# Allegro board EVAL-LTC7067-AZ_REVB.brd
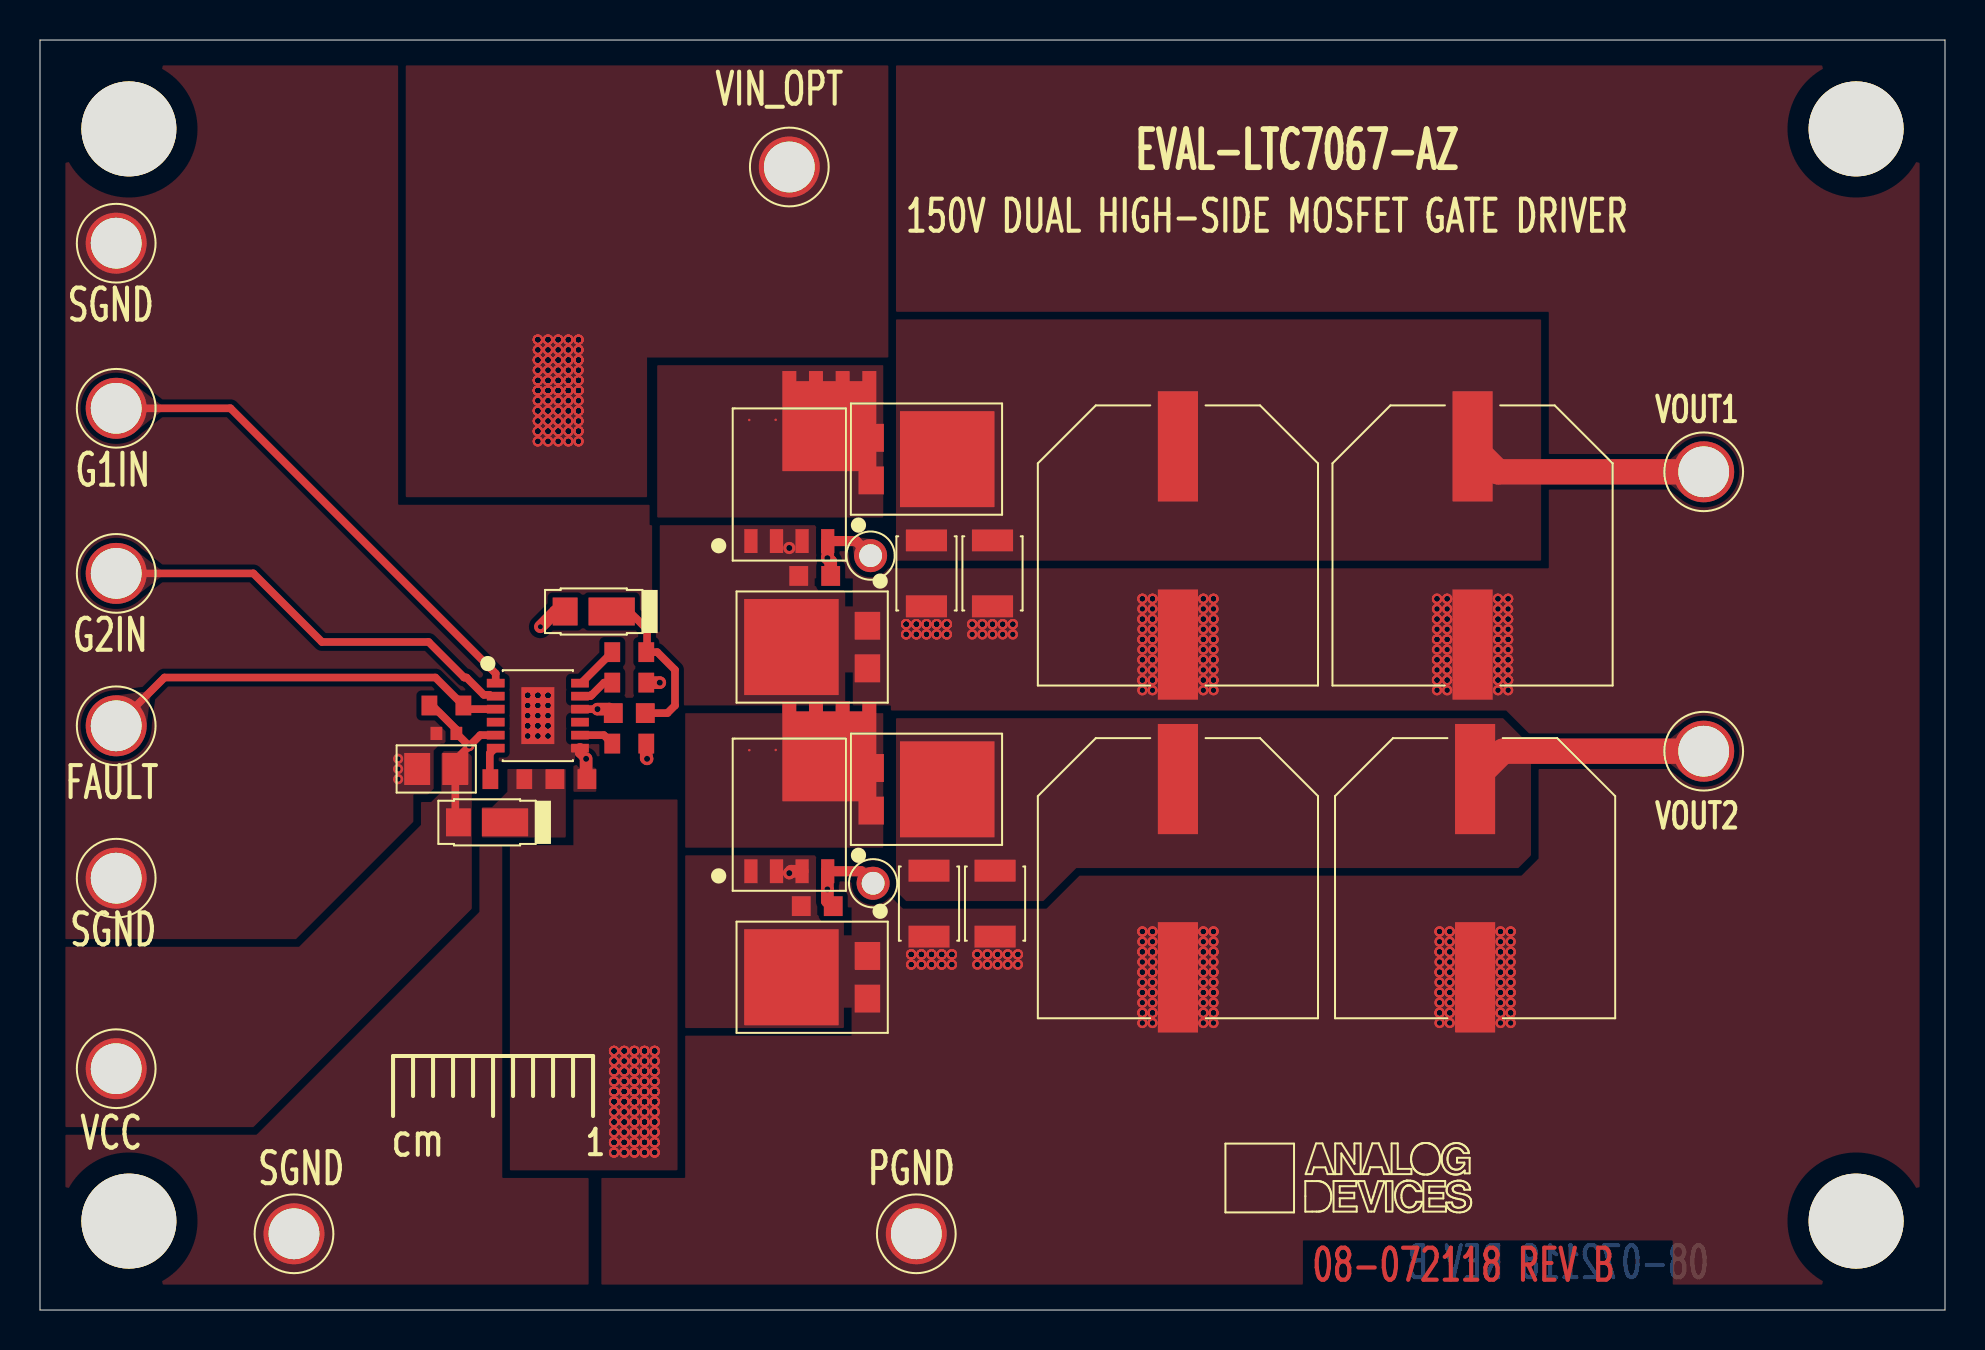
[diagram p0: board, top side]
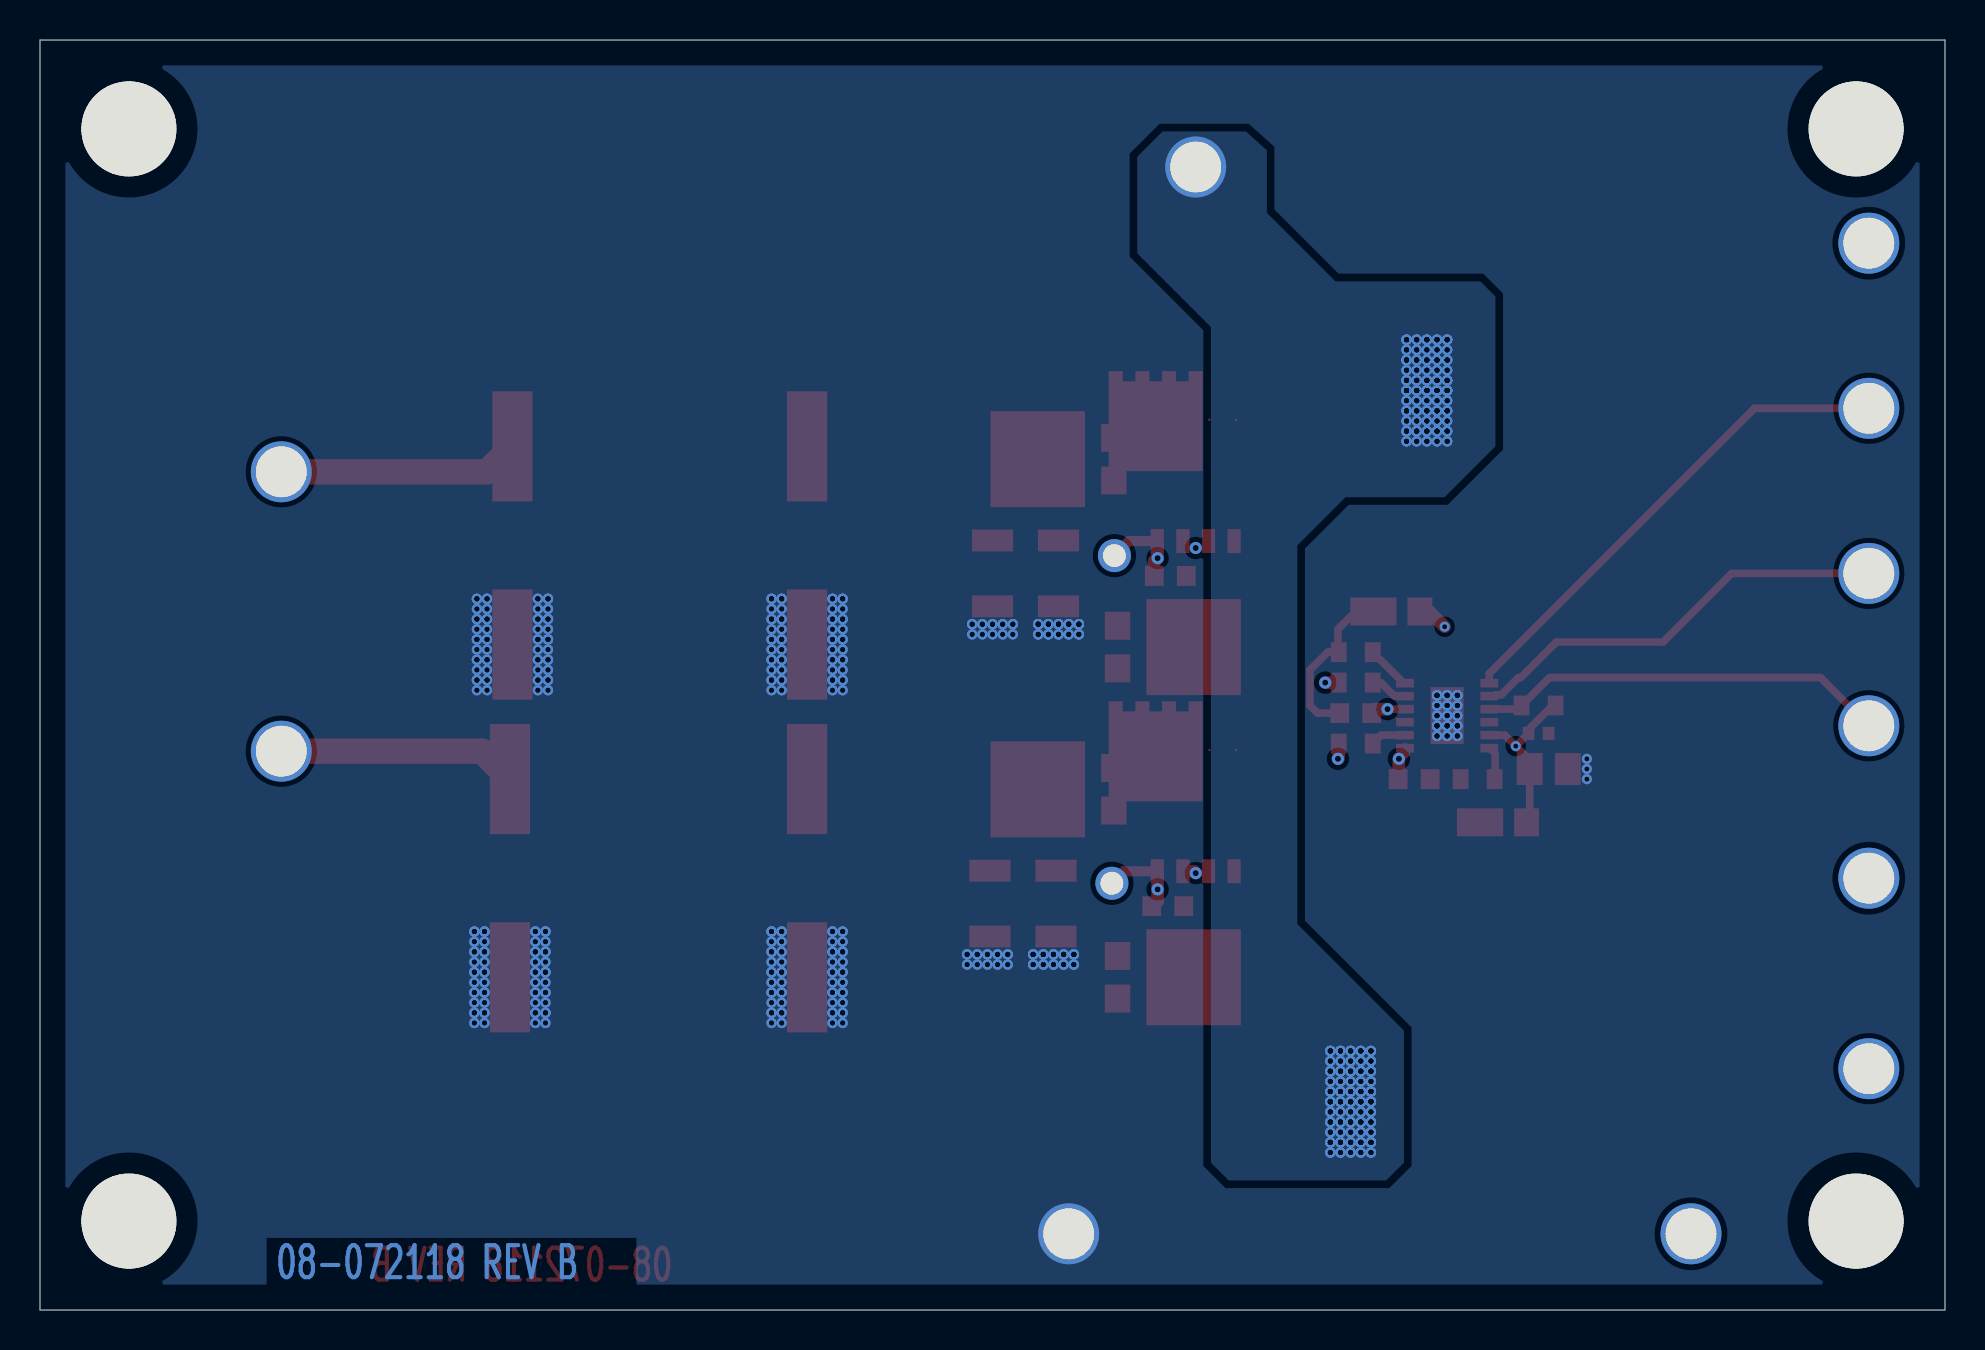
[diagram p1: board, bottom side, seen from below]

Outline 95.25 x 63.5 mm; copper layers: TOP, LAYER_2, LAYER_3, BOTTOM. Coordinates in mm from the lower left corner of the outline.
Outline path: 0,63.5 0,0 95.25,0 95.25,63.5 0,63.5

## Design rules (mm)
constraint set DEFAULT: min track width 0.203

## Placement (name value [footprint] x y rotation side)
C1  1uF  [C0402]  20.32 28.83 180 top
C2  10uF  [C0805H53]  19.81 27.05 180 top
C3  1uF  [C0603]  26.54 26.54 0 top
C4  1uF  [C0603]  29.46 29.84 180 top
C5  3300PF  [C0603]  38.73 36.7 180 top
C6  3300PF  [C0603]  38.86 20.19 180 top
C7  10UF  [C1210H106]  44.32 36.83 270 top
C8  10UF  [C1210H106]  47.75 20.32 270 top
C9  10UF  [C1210H106]  47.62 36.83 270 top
C10  10UF  [C1210H106]  44.45 20.32 270 top
C11  47UF  [CPLSMSQ531H551]  56.9 38.23 270 top
C12  47UF  [CPLSMSQ531H551]  56.9 21.59 270 top
C13  47UF  [CPLSMSQ531H551]  71.63 38.23 270 top
C14  47UF  [CPLSMSQ531H551]  71.75 21.59 270 top
D1  V10PM15-M3/H  [TO-277A]  44.32 42.55 0 top
D2  V10PM15-M3/H  [TO-277A]  44.32 26.04 0 top
D3  V10PM15-M3/H  [TO-277A]  38.61 33.15 180 top
D4  V10PM15-M3/H  [TO-277A]  38.61 16.64 180 top
D5  S115FP  [SOD123HE]  22.35 24.38 180 top
D6  S115FP  [SOD123HE]  27.69 34.92 180 top
G1  TESTPAD  [TPC65D45]  41.53 37.72 0 top
G2  TESTPAD  [TPC65D45]  41.66 21.34 0 top
NOREF  -  []  -219.18 315.6 0 top
NOREF#2  -  []  0 0 90 top
NOREF#3  -  []  -240.03 120.65 0 top
NOREF#4  -  []  51.44 332.11 0 top
NOREF#5  -  []  20.95 5.71 0 top
NOREF#6  -  [unnamed#2]  4.45 4.45 0 top
NOREF#7  -  []  25.53 -11.3 0 top
NOREF#8  -  []  -90.81 -85.09 0 top
NOREF#9  -  []  -247.01 -158.75 0 top
NOREF#10  -  []  -0.13 0.13 0 top
NOREF#11  -  []  -247.01 -158.75 0 top
NOREF#12  -  []  -220 266.04 0 top
NOREF#13  -  []  -217.17 341 0 top
NOREF#14  -  [unnamed#2]  90.81 59.05 0 top
NOREF#15  -  [unnamed#2]  4.45 59.05 0 top
NOREF#16  -  []  323.85 306.07 0 top
NOREF#17  -  []  -247.01 -158.75 0 top
NOREF#18  -  [unnamed#2]  90.81 4.45 0 top
Q1  BSC160N15NS5ATMA1  [SON8]  37.47 41.27 0 top
Q2  BSC160N15NS5ATMA1  [SON8]  37.47 24.77 0 top
R2  100K  [R0603]  20.32 30.23 0 top
R5  0  [R0603]  23.37 26.54 0 top
R6  0  [R0603]  29.46 31.37 180 top
R7  0  [R0603]  29.46 32.89 180 top
R8  0  [R0603]  29.46 28.32 180 top
TP1  2501-2-00-80-00-00-07-0  [CNMILLMAX2501]  3.81 45.09 0 top
TP2  2501-2-00-80-00-00-07-0  [CNMILLMAX2501]  3.81 36.83 0 top
TP3  2501-2-00-80-00-00-07-0  [CNMILLMAX2501]  3.81 12.06 0 top
TP4  2501-2-00-80-00-00-07-0  [CNMILLMAX2501]  37.47 57.15 0 top
TP5  2501-2-00-80-00-00-07-0  [CNMILLMAX2501]  43.81 3.81 0 top
TP6  2501-2-00-80-00-00-07-0  [CNMILLMAX2501]  3.81 21.59 0 top
TP7  2501-2-00-80-00-00-07-0  [CNMILLMAX2501]  83.19 41.91 0 top
TP8  2501-2-00-80-00-00-07-0  [CNMILLMAX2501]  83.19 27.94 0 top
TP9  2501-2-00-80-00-00-07-0  [CNMILLMAX2501]  3.81 53.34 0 top
TP10  2501-2-00-80-00-00-07-0  [CNMILLMAX2501]  12.7 3.81 0 top
TP11  2501-2-00-80-00-00-07-0  [CNMILLMAX2501]  3.81 29.21 0 top
U1  LTC7067RMSE#WPBF  [MSOP12_PAD2_845X1_651_05-08-1666]  24.89 29.72 270 top

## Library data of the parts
C1 = CAP: User Part Number: UPN; Tolerance: 20; alternate symbols: (C0402L); part number: CAP_SM-1UF,16V,20,E020695,C0402; tolerance: 20
C2 = CAP: Tolerance: 10; User Part Number: UPN; alternate symbols: (); part number: CAP_SM-10UF,16V,10,E006166,C0805H53; tolerance: 10
C3 C4 = CAP: User Part Number: UPN; Tolerance: 10; alternate symbols: (C0603L); part number: CAP_SM-1UF,16V,10,E020111,C0603; tolerance: 10
C5 C6 = CAP: User Part Number: UPN; Tolerance: 10; alternate symbols: (C0603L); part number: CAP_SM-3300PF,25V,10,E058968,C0603; tolerance: 10
C7-C10 = CAP: Tolerance: 10; User Part Number: UPN; alternate symbols: (C1210L); part number: CAP_SM-10UF,100V,10,E044329,C1210H106; tolerance: 10
C11-C14 = CAPP: Tolerance: 20; User Part Number: UPN; alternate symbols: (); part number: CAPP_SM-47UF,100V,20,E049289,CPLSMSQ531H551; tolerance: 20
D1-D4 = DIOSCHOTTKY_3P: User Part Number: UPN; Tolerance: N/A; alternate symbols: (); part number: DIOSCHOTTKY_3P_SM-V10PM15-M3/H,150V,N/A,E057965,TO-277A; tolerance: N/A
D5 D6 = DIOSCHOTTKY: User Part Number: UPN; Tolerance: N/A; alternate symbols: (); part number: DIOSCHOTTKY_SM-S115FP,150V,N/A,E046225,SOD123HE; tolerance: N/A
G1 G2 = NCTESTPAD: Tolerance: N/A; User Part Number: UPN; alternate symbols: (); part number: NCTESTPAD_TH-TESTPAD,E013404,TPC65D45; tolerance: N/A
Q1 Q2 = TRANNMOSFET_8P_V2: Tolerance: N/A; User Part Number: UPN; alternate symbols: (); part number: TRANNMOSFET_8P_V2_SM-BSC160N15NS5ATMA1,E051660,SON8; tolerance: N/A
R2 = RES: User Part Number: UPN; Tolerance: 1; alternate symbols: (R0603L); part number: RES_SM-100K,E010279,1/10W,1,R0603; tolerance: 1
R5-R8 = RES: User Part Number: UPN; Tolerance: N/A; alternate symbols: (R0603L); part number: RES_SM-0,E005803,N/A,N/A,R0603; tolerance: N/A
TP1-TP11 = CNTP1P: User Part Number: UPN; Tolerance: N/A; alternate symbols: (); part number: CNTP1P_TH-2501-2-00-80-00-00-07-0,E031108,CNMILLMAX2501; tolerance: N/A
U1 = ADLTC7067: Tolerance: N/A; User Part Number: UPN; alternate symbols: (); part number: ADLTC7067_SM-LTC7067RMSE#WPBF,E057879,MSOP12_PAD2_845X1_651_05-08-1666; tolerance: N/A

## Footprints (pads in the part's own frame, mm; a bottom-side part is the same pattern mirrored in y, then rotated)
C0402
  rect 0.584x0.66 smd: 1(-0.5,0) 2(0.5,0)
C0603
  rect 0.94x0.991 smd: 1(-0.8,0) 2(0.8,0)
C0805H53
  rect 1.295x1.6 smd: 1(-0.953,0) 2(0.953,0)
C1210H106
  rect 1.092x2.057 smd: 1(-1.646,0) 2(1.646,0)
CNMILLMAX2501
  round 3.048 hole 2.54: 1(0,0)
CPLSMSQ531H551
  rect 5.512x2.007 smd: N(4.956,0) P(-4.956,0)
MSOP12_PAD2_845X1_651_05-08-1666
  rect 0.432x0.889 smd: 1(-1.625,-2.107) 2(-0.975,-2.107) 3(-0.325,-2.107) 4(0.325,-2.107) 5(0.975,-2.107) 6(1.625,-2.107) 7(1.625,2.107) 8(0.975,2.107) 9(0.325,2.107) 10(-0.325,2.107) 11(-0.975,2.107) 12(-1.625,2.107)
  rect 2.845x1.651 smd: 13(0,0)
R0603
  rect 0.787x0.991 smd: 1(-0.85,0) 2(0.85,0)
SOD123HE
  rect 1.245x1.397 smd: A(1.431,0)
  rect 2.311x1.397 smd: C(-0.897,0)
SON8
  rect 0.66x1.194 smd: 1(-1.92,-2.828) 2(-0.64,-2.828) 3(0.64,-2.828) 4(1.92,-2.828)
  custom 1.175x1.175 smd: 5(2,3.171)
  round 0.127 smd: 6(0.678,3.211) 7(-0.68,3.236) 8(-2.002,3.223)
TO-277A
  rect 1.27x1.397 smd: 1(-2.765,-1.065) 2(-2.765,1.065)
  rect 4.724x4.801 smd: 3(1.038,0)
TPC65D45
  round 1.651 hole 1.143: 1(0,0)
unnamed#2
  round 4.75 hole 4.75 unplated: (0,0)

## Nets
GND_SIGNAL: C1.2(N2) C2.2(N2) C3.2(N2) C4.2(N2) C5.2(N2) C6.2(N2) C7.2(N2) C8.2(N2) C9.2(N2) C10.2(N2) C11.N(N2) C12.N(N2) C13.N(N2) C14.N(N2) D3.1 D3.2 D3.3(C) D4.1 D4.2 D4.3(C) Q1.1 Q1.2 Q1.3(S3) Q2.1 Q2.2 Q2.3(S3) TP5.1(N1) TP6.1(N1) TP9.1(N1) TP10.1(N1) U1.7 U1.10 U1.13
VCC: C1.1 C2.1 D5.A(P) D6.A(P) R2.1 TP3.1(N1) U1.5(VCC)
VIN_OPT: TP4.1(N1)
G1: C5.1 G1.1(N1) Q1.4 R6.1
G2: C6.1 G2.1(N1) Q2.4 R8.1
Q1_D: D1.1 D1.2 Q1.5 Q1.6 Q1.7 Q1.8
Q2_D: D2.1 D2.2 Q2.5 Q2.6 Q2.7 Q2.8
UNNAMED_2_ADLTC7067_I79_FLTN: R2.2(N2) TP11.1(N1) U1.3
UNNAMED_2_ADLTC7067_I79_G1: R6.2(N2) U1.11
UNNAMED_2_ADLTC7067_I79_G1IN: TP1.1(N1) U1.1
UNNAMED_2_ADLTC7067_I79_G1VCC: R7.2(N2) U1.12
UNNAMED_2_ADLTC7067_I79_G2: R8.2(N2) U1.8
UNNAMED_2_ADLTC7067_I79_G2IN: TP2.1(N1) U1.2
UNNAMED_2_ADLTC7067_I79_G2VCC: R5.1 U1.6
UNNAMED_2_CAP_I57_N1: C7.1 C9.1 C11.P C13.P D1.3(C) TP7.1(N1)
UNNAMED_2_CAP_I59_N1: C8.1 C10.1 C12.P C14.P D2.3(C) TP8.1(N1)
UNNAMED_2_DIOSCHOTTKY_I13_N: C3.1 D5.C R5.2(N2)
UNNAMED_2_DIOSCHOTTKY_I25_N: C4.1 D6.C R7.1

Pads without a net: U1 4 9

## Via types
v1: diameter 0.61, hole 0.305, TOP to BOTTOM, 8 vias
v2: diameter 0.508, hole 0.254, TOP to BOTTOM, 1469 vias

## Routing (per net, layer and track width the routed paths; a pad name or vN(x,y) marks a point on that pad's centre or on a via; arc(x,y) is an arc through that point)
GND_SIGNAL: length 33.7
  TOP w0.381: U1.10 v1(27.88,30.04)
  TOP w0.508: v1(27.3,27.56) 27,27.87 U1.7
  TOP w0.635: Q2.3 37.56,21.94 v1(37.47,21.84) ; v1(27.3,27.56) 27.3,26.58 C3.2 ; C4.2 28.47,30.04 v1(27.88,30.04)
  LAYER_3 w0.635: v1(37.47,38.1) 37.47,36.32 33.4,32.26 30.09,32.26 v1(27.88,30.04) ; v1(27.3,27.56) 29.08,27.56 29.92,28.4 30.7,28.4 31.24,27.86 31.24,23.75 33.15,21.84 v1(37.47,21.84)
  vias: v2(17.91,27.56) v2(17.91,27.05) v2(17.91,26.54) v2(24.38,30.73) v2(24.38,30.73) v2(24.38,30.73) v2(24.38,30.73) v2(24.38,30.73) v2(24.38,30.73) v2(24.38,30.73) v2(24.38,30.73) v2(24.38,30.23) v2(24.38,30.23) v2(24.38,30.23) v2(24.38,30.23) v2(24.38,29.72) v2(24.38,29.72) v2(24.38,29.72) v2(24.38,29.72) v2(24.38,29.21) v2(24.38,29.21) v2(24.38,29.21) v2(24.38,29.21) v2(24.38,29.21) v2(24.38,29.21) v2(24.38,29.21) v2(24.38,29.21) v2(24.38,28.7) v2(24.38,28.7) v2(24.38,28.7) v2(24.38,28.7) v2(24.89,30.73) v2(24.89,30.73) v2(24.89,30.73) v2(24.89,30.73) v2(24.89,30.73) v2(24.89,30.73) v2(24.89,30.73) v2(24.89,30.73) v2(24.89,30.23) v2(24.89,30.23) v2(24.89,30.23) v2(24.89,30.23) v2(24.89,29.72) v2(24.89,29.72) v2(24.89,29.72) v2(24.89,29.72) v2(24.89,29.21) v2(24.89,29.21) v2(24.89,29.21) v2(24.89,29.21) v2(24.89,29.21) v2(24.89,29.21) v2(24.89,29.21) v2(24.89,29.21) v2(24.89,28.7) v2(24.89,28.7) v2(24.89,28.7) v2(24.89,28.7) v2(25.4,30.73) v2(25.4,30.73) v2(25.4,30.73) v2(25.4,30.73) v2(25.4,30.73) v2(25.4,30.73) v2(25.4,30.73) v2(25.4,30.73) v2(25.4,30.23) v2(25.4,30.23) v2(25.4,30.23) v2(25.4,30.23) v2(25.4,29.72) v2(25.4,29.72) v2(25.4,29.72) v2(25.4,29.72) v2(25.4,29.21) v2(25.4,29.21) v2(25.4,29.21) v2(25.4,29.21) v2(25.4,29.21) v2(25.4,29.21) v2(25.4,29.21) v2(25.4,29.21) v2(25.4,28.7) v2(25.4,28.7) v2(25.4,28.7) v2(25.4,28.7) v2(43.31,34.29) v2(43.31,34.29) v2(43.31,34.29) v2(43.31,34.29) v2(43.31,34.29) v2(43.31,34.29) v2(43.31,34.29) v2(43.31,34.29) v2(43.31,33.78) v2(43.31,33.78) v2(43.31,33.78) v2(43.31,33.78) v2(43.56,17.78) v2(43.56,17.78) v2(43.56,17.78) v2(43.56,17.78) v2(43.56,17.78) v2(43.56,17.78) v2(43.56,17.78) v2(43.56,17.78) v2(43.56,17.27) v2(43.56,17.27) v2(43.56,17.27) v2(43.56,17.27) v2(43.81,34.29) v2(43.81,34.29) v2(43.81,34.29) v2(43.81,34.29) v2(43.81,34.29) v2(43.81,34.29) v2(43.81,34.29) v2(43.81,34.29) v2(43.81,33.78) v2(43.81,33.78) v2(43.81,33.78) v2(43.81,33.78) v2(44.07,17.78) v2(44.07,17.78) v2(44.07,17.78) v2(44.07,17.78) v2(44.07,17.78) v2(44.07,17.78) v2(44.07,17.78) v2(44.07,17.78) v2(44.07,17.27) v2(44.07,17.27) v2(44.07,17.27) v2(44.07,17.27) v2(44.32,34.29) v2(44.32,34.29) v2(44.32,34.29) v2(44.32,34.29) v2(44.32,34.29) v2(44.32,34.29) v2(44.32,34.29) v2(44.32,34.29) v2(44.32,33.78) v2(44.32,33.78) v2(44.32,33.78) v2(44.32,33.78) v2(44.58,17.78) v2(44.58,17.78) v2(44.58,17.78) v2(44.58,17.78) v2(44.58,17.78) v2(44.58,17.78) v2(44.58,17.78) v2(44.58,17.78) v2(44.58,17.27) v2(44.58,17.27) v2(44.58,17.27) v2(44.58,17.27) v2(44.83,34.29) v2(44.83,34.29) v2(44.83,34.29) v2(44.83,34.29) v2(44.83,34.29) v2(44.83,34.29) v2(44.83,34.29) v2(44.83,34.29) v2(44.83,33.78) v2(44.83,33.78) v2(44.83,33.78) v2(44.83,33.78) v2(45.09,17.78) v2(45.09,17.78) v2(45.09,17.78) v2(45.09,17.78) v2(45.09,17.78) v2(45.09,17.78) v2(45.09,17.78) v2(45.09,17.78) v2(45.09,17.27) v2(45.09,17.27) v2(45.09,17.27) v2(45.09,17.27) v2(45.34,34.29) v2(45.34,34.29) v2(45.34,34.29) v2(45.34,34.29) v2(45.34,34.29) v2(45.34,34.29) v2(45.34,34.29) v2(45.34,34.29) v2(45.34,33.78) v2(45.34,33.78) v2(45.34,33.78) v2(45.34,33.78) v2(45.59,17.78) v2(45.59,17.78) v2(45.59,17.78) v2(45.59,17.78) v2(45.59,17.78) v2(45.59,17.78) v2(45.59,17.78) v2(45.59,17.78) v2(45.59,17.27) v2(45.59,17.27) v2(45.59,17.27) v2(45.59,17.27) v2(46.61,34.29) v2(46.61,34.29) v2(46.61,34.29) v2(46.61,34.29) v2(46.61,33.78) v2(46.61,33.78) v2(46.86,17.78) v2(46.86,17.78) v2(46.86,17.78) v2(46.86,17.78) v2(46.86,17.27) v2(46.86,17.27) v2(47.12,34.29) v2(47.12,34.29) v2(47.12,34.29) v2(47.12,34.29) v2(47.12,33.78) v2(47.12,33.78) v2(47.37,17.78) v2(47.37,17.78) v2(47.37,17.78) v2(47.37,17.78) v2(47.37,17.27) v2(47.37,17.27) v2(47.62,34.29) v2(47.62,34.29) v2(47.62,34.29) v2(47.62,34.29) v2(47.62,33.78) v2(47.62,33.78) v2(47.88,17.78) v2(47.88,17.78) v2(47.88,17.78) v2(47.88,17.78) v2(47.88,17.27) v2(47.88,17.27) v2(48.13,34.29) v2(48.13,34.29) v2(48.13,34.29) v2(48.13,34.29) v2(48.13,33.78) v2(48.13,33.78) v2(48.39,17.78) v2(48.39,17.78) v2(48.39,17.78) v2(48.39,17.78) v2(48.39,17.27) v2(48.39,17.27) v2(48.64,34.29) v2(48.64,34.29) v2(48.64,34.29) v2(48.64,34.29) v2(48.64,33.78) v2(48.64,33.78) v2(48.9,17.78) v2(48.9,17.78) v2(48.9,17.78) v2(48.9,17.78) v2(48.9,17.27) v2(48.9,17.27) v2(55.12,35.56) v2(55.12,35.56) v2(55.12,35.56) v2(55.12,35.56) v2(55.12,35.05) v2(55.12,35.05) v2(55.12,34.54) v2(55.12,34.54) v2(55.12,34.54) v2(55.12,34.54) v2(55.12,34.04) v2(55.12,34.04) v2(55.12,33.53) v2(55.12,33.53) v2(55.12,33.53) v2(55.12,33.53) v2(55.12,33.02) v2(55.12,33.02) v2(55.12,32.51) v2(55.12,32.51) v2(55.12,32.51) v2(55.12,32.51) v2(55.12,32) v2(55.12,32) v2(55.12,31.5) v2(55.12,31.5) v2(55.12,31.5) v2(55.12,31.5) v2(55.12,30.99) v2(55.12,30.99) v2(55.12,18.92) v2(55.12,18.92) v2(55.12,18.92) v2(55.12,18.92) v2(55.12,18.41) v2(55.12,18.41) v2(55.12,17.91) v2(55.12,17.91) v2(55.12,17.91) v2(55.12,17.91) v2(55.12,17.4) v2(55.12,17.4) v2(55.12,16.89) v2(55.12,16.89) v2(55.12,16.89) v2(55.12,16.89) v2(55.12,16.38) v2(55.12,16.38) v2(55.12,15.88) v2(55.12,15.88) v2(55.12,15.88) v2(55.12,15.88) v2(55.12,15.37) v2(55.12,15.37) v2(55.12,14.86) v2(55.12,14.86) v2(55.12,14.86) v2(55.12,14.86) v2(55.12,14.35) v2(55.12,14.35) v2(55.63,35.56) v2(55.63,35.56) v2(55.63,35.56) v2(55.63,35.56) v2(55.63,35.05) v2(55.63,35.05) v2(55.63,34.54) v2(55.63,34.54) v2(55.63,34.54) v2(55.63,34.54) v2(55.63,34.04) v2(55.63,34.04) v2(55.63,33.53) v2(55.63,33.53) v2(55.63,33.53) v2(55.63,33.53) v2(55.63,33.02) v2(55.63,33.02) v2(55.63,32.51) v2(55.63,32.51) v2(55.63,32.51) v2(55.63,32.51) v2(55.63,32) v2(55.63,32) v2(55.63,31.5) v2(55.63,31.5) v2(55.63,31.5) v2(55.63,31.5) v2(55.63,30.99) v2(55.63,30.99) v2(55.63,18.92) v2(55.63,18.92) v2(55.63,18.92) v2(55.63,18.92) v2(55.63,18.41) v2(55.63,18.41) v2(55.63,17.91) v2(55.63,17.91) v2(55.63,17.91) v2(55.63,17.91) v2(55.63,17.4) v2(55.63,17.4) v2(55.63,16.89) v2(55.63,16.89) v2(55.63,16.89) v2(55.63,16.89) v2(55.63,16.38) v2(55.63,16.38) v2(55.63,15.88) v2(55.63,15.88) v2(55.63,15.88) v2(55.63,15.88) v2(55.63,15.37) v2(55.63,15.37) v2(55.63,14.86) v2(55.63,14.86) v2(55.63,14.86) v2(55.63,14.86) v2(55.63,14.35) v2(55.63,14.35) v2(58.17,35.56) v2(58.17,35.56) v2(58.17,35.56) v2(58.17,35.56) v2(58.17,35.05) v2(58.17,35.05) v2(58.17,34.54) v2(58.17,34.54) v2(58.17,34.54) v2(58.17,34.54) v2(58.17,34.04) v2(58.17,34.04) v2(58.17,33.53) v2(58.17,33.53) v2(58.17,33.53) v2(58.17,33.53) v2(58.17,33.02) v2(58.17,33.02) v2(58.17,32.51) v2(58.17,32.51) v2(58.17,32.51) v2(58.17,32.51) v2(58.17,32) v2(58.17,32) v2(58.17,31.5) v2(58.17,31.5) v2(58.17,31.5) v2(58.17,31.5) v2(58.17,30.99) v2(58.17,30.99) v2(58.17,18.92) v2(58.17,18.92) v2(58.17,18.92) v2(58.17,18.92) v2(58.17,18.41) v2(58.17,18.41) v2(58.17,17.91) v2(58.17,17.91) v2(58.17,17.91) v2(58.17,17.91) v2(58.17,17.4) v2(58.17,17.4) v2(58.17,16.89) v2(58.17,16.89) v2(58.17,16.89) v2(58.17,16.89) v2(58.17,16.38) v2(58.17,16.38) v2(58.17,15.88) v2(58.17,15.88) v2(58.17,15.88) v2(58.17,15.88) v2(58.17,15.37) v2(58.17,15.37) v2(58.17,14.86) v2(58.17,14.86) v2(58.17,14.86) v2(58.17,14.86) v2(58.17,14.35) v2(58.17,14.35) v2(58.67,35.56) v2(58.67,35.56) v2(58.67,35.56) v2(58.67,35.56) v2(58.67,35.05) v2(58.67,35.05) v2(58.67,34.54) v2(58.67,34.54) v2(58.67,34.54) v2(58.67,34.54) v2(58.67,34.04) v2(58.67,34.04) v2(58.67,33.53) v2(58.67,33.53) v2(58.67,33.53) v2(58.67,33.53) v2(58.67,33.02) v2(58.67,33.02) v2(58.67,32.51) v2(58.67,32.51) v2(58.67,32.51) v2(58.67,32.51) v2(58.67,32) v2(58.67,32) v2(58.67,31.5) v2(58.67,31.5) v2(58.67,31.5) v2(58.67,31.5) v2(58.67,30.99) v2(58.67,30.99) v2(58.67,18.92) v2(58.67,18.92) v2(58.67,18.92) v2(58.67,18.92) v2(58.67,18.41) v2(58.67,18.41) v2(58.67,17.91) v2(58.67,17.91) v2(58.67,17.91) v2(58.67,17.91) v2(58.67,17.4) v2(58.67,17.4) v2(58.67,16.89) v2(58.67,16.89) v2(58.67,16.89) v2(58.67,16.89) v2(58.67,16.38) v2(58.67,16.38) v2(58.67,15.88) v2(58.67,15.88) v2(58.67,15.88) v2(58.67,15.88) v2(58.67,15.37) v2(58.67,15.37) v2(58.67,14.86) v2(58.67,14.86) v2(58.67,14.86) v2(58.67,14.86) v2(58.67,14.35) v2(58.67,14.35) v2(69.85,35.56) v2(69.85,35.56) v2(69.85,35.56) v2(69.85,35.56) v2(69.85,35.05) v2(69.85,35.05) v2(69.85,34.54) v2(69.85,34.54) v2(69.85,34.54) v2(69.85,34.54) v2(69.85,34.04) v2(69.85,34.04) v2(69.85,33.53) v2(69.85,33.53) v2(69.85,33.53) v2(69.85,33.53) v2(69.85,33.02) v2(69.85,33.02) v2(69.85,32.51) v2(69.85,32.51) v2(69.85,32.51) v2(69.85,32.51) v2(69.85,32) v2(69.85,32) v2(69.85,31.5) v2(69.85,31.5) v2(69.85,31.5) v2(69.85,31.5) v2(69.85,30.99) v2(69.85,30.99) v2(69.98,18.92) v2(69.98,18.92) v2(69.98,18.92) v2(69.98,18.92) v2(69.98,18.41) v2(69.98,18.41) v2(69.98,17.91) v2(69.98,17.91) v2(69.98,17.91) v2(69.98,17.91) v2(69.98,17.4) v2(69.98,17.4) v2(69.98,16.89) v2(69.98,16.89) v2(69.98,16.89) v2(69.98,16.89) v2(69.98,16.38) v2(69.98,16.38) v2(69.98,15.88) v2(69.98,15.88) v2(69.98,15.88) v2(69.98,15.88) v2(69.98,15.37) v2(69.98,15.37) v2(69.98,14.86) v2(69.98,14.86) v2(69.98,14.86) v2(69.98,14.86) v2(69.98,14.35) v2(69.98,14.35) v2(70.36,35.56) v2(70.36,35.56) v2(70.36,35.56) v2(70.36,35.56) v2(70.36,35.05) v2(70.36,35.05) v2(70.36,34.54) v2(70.36,34.54) v2(70.36,34.54) v2(70.36,34.54) v2(70.36,34.04) v2(70.36,34.04) v2(70.36,33.53) v2(70.36,33.53) v2(70.36,33.53) v2(70.36,33.53) v2(70.36,33.02) v2(70.36,33.02) v2(70.36,32.51) v2(70.36,32.51) v2(70.36,32.51) v2(70.36,32.51) v2(70.36,32) v2(70.36,32) v2(70.36,31.5) v2(70.36,31.5) v2(70.36,31.5) v2(70.36,31.5) v2(70.36,30.99) v2(70.36,30.99) v2(70.48,18.92) v2(70.48,18.92) v2(70.48,18.92) v2(70.48,18.92) v2(70.48,18.41) v2(70.48,18.41) v2(70.48,17.91) v2(70.48,17.91) v2(70.48,17.91) v2(70.48,17.91) v2(70.48,17.4) v2(70.48,17.4) v2(70.48,16.89) v2(70.48,16.89) v2(70.48,16.89) v2(70.48,16.89) v2(70.48,16.38) v2(70.48,16.38) v2(70.48,15.88) v2(70.48,15.88) v2(70.48,15.88) v2(70.48,15.88) v2(70.48,15.37) v2(70.48,15.37) v2(70.48,14.86) v2(70.48,14.86) v2(70.48,14.86) v2(70.48,14.86) v2(70.48,14.35) v2(70.48,14.35) v2(72.9,35.56) v2(72.9,35.56) v2(72.9,35.56) v2(72.9,35.56) v2(72.9,35.05) v2(72.9,35.05) v2(72.9,34.54) v2(72.9,34.54) v2(72.9,34.54) v2(72.9,34.54) v2(72.9,34.04) v2(72.9,34.04) v2(72.9,33.53) v2(72.9,33.53) v2(72.9,33.53) v2(72.9,33.53) v2(72.9,33.02) v2(72.9,33.02) v2(72.9,32.51) v2(72.9,32.51) v2(72.9,32.51) v2(72.9,32.51) v2(72.9,32) v2(72.9,32) v2(72.9,31.5) v2(72.9,31.5) v2(72.9,31.5) v2(72.9,31.5) v2(72.9,30.99) v2(72.9,30.99) v2(73.03,18.92) v2(73.03,18.92) v2(73.03,18.92) v2(73.03,18.92) v2(73.03,18.41) v2(73.03,18.41) v2(73.03,17.91) v2(73.03,17.91) v2(73.03,17.91) v2(73.03,17.91) v2(73.03,17.4) v2(73.03,17.4) v2(73.03,16.89) v2(73.03,16.89) v2(73.03,16.89) v2(73.03,16.89) v2(73.03,16.38) v2(73.03,16.38) v2(73.03,15.88) v2(73.03,15.88) v2(73.03,15.88) v2(73.03,15.88) v2(73.03,15.37) v2(73.03,15.37) v2(73.03,14.86) v2(73.03,14.86) v2(73.03,14.86) v2(73.03,14.86) v2(73.03,14.35) v2(73.03,14.35) v2(73.41,35.56) v2(73.41,35.56) v2(73.41,35.56) v2(73.41,35.56) v2(73.41,35.05) v2(73.41,35.05) v2(73.41,34.54) v2(73.41,34.54) v2(73.41,34.54) v2(73.41,34.54) v2(73.41,34.04) v2(73.41,34.04) v2(73.41,33.53) v2(73.41,33.53) v2(73.41,33.53) v2(73.41,33.53) v2(73.41,33.02) v2(73.41,33.02) v2(73.41,32.51) v2(73.41,32.51) v2(73.41,32.51) v2(73.41,32.51) v2(73.41,32) v2(73.41,32) v2(73.41,31.5) v2(73.41,31.5) v2(73.41,31.5) v2(73.41,31.5) v2(73.41,30.99) v2(73.41,30.99) v2(73.53,18.92) v2(73.53,18.92) v2(73.53,18.92) v2(73.53,18.92) v2(73.53,18.41) v2(73.53,18.41) v2(73.53,17.91) v2(73.53,17.91) v2(73.53,17.91) v2(73.53,17.91) v2(73.53,17.4) v2(73.53,17.4) v2(73.53,16.89) v2(73.53,16.89) v2(73.53,16.89) v2(73.53,16.89) v2(73.53,16.38) v2(73.53,16.38) v2(73.53,15.88) v2(73.53,15.88) v2(73.53,15.88) v2(73.53,15.88) v2(73.53,15.37) v2(73.53,15.37) v2(73.53,14.86) v2(73.53,14.86) v2(73.53,14.86) v2(73.53,14.86) v2(73.53,14.35) v2(73.53,14.35)
VCC: length 18.8
  TOP w0.381: v2(21.46,28.19) 22.01,28.74 U1.5 ; v2(21.46,28.19) 20.76,27.5 C2.1 20.76,24.54 D5.A 20.92,24.42 ; v2(21.46,28.19) 20.83,28.83 C1.1 20.82,29.02 19.61,30.23 R2.1
  TOP w0.635: v2(25.02,34.16) 25.78,34.92 D6.A
  LAYER_3 w0.508: v2(21.46,28.19) 21.59,28.32 21.59,32.64 23.11,34.16 v2(25.02,34.16)
VIN_OPT:
  vias: v2(24.89,48.51) v2(24.89,48.51) v2(24.89,48.51) v2(24.89,48.51) v2(24.89,48.51) v2(24.89,48.51) v2(24.89,48.51) v2(24.89,48.51) v2(24.89,48.01) v2(24.89,48.01) v2(24.89,48.01) v2(24.89,48.01) v2(24.89,47.5) v2(24.89,47.5) v2(24.89,47.5) v2(24.89,47.5) v2(24.89,47.5) v2(24.89,47.5) v2(24.89,47.5) v2(24.89,47.5) v2(24.89,46.99) v2(24.89,46.99) v2(24.89,46.99) v2(24.89,46.99) v2(24.89,46.48) v2(24.89,46.48) v2(24.89,46.48) v2(24.89,46.48) v2(24.89,46.48) v2(24.89,46.48) v2(24.89,46.48) v2(24.89,46.48) v2(24.89,45.97) v2(24.89,45.97) v2(24.89,45.97) v2(24.89,45.97) v2(24.89,45.97) v2(24.89,45.97) v2(24.89,45.97) v2(24.89,45.97) v2(24.89,45.97) v2(24.89,45.97) v2(24.89,45.97) v2(24.89,45.97) v2(24.89,45.47) v2(24.89,45.47) v2(24.89,45.47) v2(24.89,45.47) v2(24.89,44.96) v2(24.89,44.96) v2(24.89,44.96) v2(24.89,44.96) v2(24.89,44.96) v2(24.89,44.96) v2(24.89,44.96) v2(24.89,44.96) v2(24.89,44.45) v2(24.89,44.45) v2(24.89,44.45) v2(24.89,44.45) v2(24.89,43.94) v2(24.89,43.94) v2(24.89,43.94) v2(24.89,43.94) v2(24.89,43.94) v2(24.89,43.94) v2(24.89,43.94) v2(24.89,43.94) v2(24.89,43.43) v2(24.89,43.43) v2(24.89,43.43) v2(24.89,43.43) v2(25.4,48.51) v2(25.4,48.51) v2(25.4,48.51) v2(25.4,48.51) v2(25.4,48.51) v2(25.4,48.51) v2(25.4,48.51) v2(25.4,48.51) v2(25.4,48.01) v2(25.4,48.01) v2(25.4,48.01) v2(25.4,48.01) v2(25.4,47.5) v2(25.4,47.5) v2(25.4,47.5) v2(25.4,47.5) v2(25.4,47.5) v2(25.4,47.5) v2(25.4,47.5) v2(25.4,47.5) v2(25.4,46.99) v2(25.4,46.99) v2(25.4,46.99) v2(25.4,46.99) v2(25.4,46.48) v2(25.4,46.48) v2(25.4,46.48) v2(25.4,46.48) v2(25.4,46.48) v2(25.4,46.48) v2(25.4,46.48) v2(25.4,46.48) v2(25.4,45.97) v2(25.4,45.97) v2(25.4,45.97) v2(25.4,45.97) v2(25.4,45.97) v2(25.4,45.97) v2(25.4,45.97) v2(25.4,45.97) v2(25.4,45.97) v2(25.4,45.97) v2(25.4,45.97) v2(25.4,45.97) v2(25.4,45.47) v2(25.4,45.47) v2(25.4,45.47) v2(25.4,45.47) v2(25.4,44.96) v2(25.4,44.96) v2(25.4,44.96) v2(25.4,44.96) v2(25.4,44.96) v2(25.4,44.96) v2(25.4,44.96) v2(25.4,44.96) v2(25.4,44.45) v2(25.4,44.45) v2(25.4,44.45) v2(25.4,44.45) v2(25.4,43.94) v2(25.4,43.94) v2(25.4,43.94) v2(25.4,43.94) v2(25.4,43.94) v2(25.4,43.94) v2(25.4,43.94) v2(25.4,43.94) v2(25.4,43.43) v2(25.4,43.43) v2(25.4,43.43) v2(25.4,43.43) v2(25.91,48.51) v2(25.91,48.51) v2(25.91,48.51) v2(25.91,48.51) v2(25.91,48.51) v2(25.91,48.51) v2(25.91,48.51) v2(25.91,48.51) v2(25.91,48.01) v2(25.91,48.01) v2(25.91,48.01) v2(25.91,48.01) v2(25.91,47.5) v2(25.91,47.5) v2(25.91,47.5) v2(25.91,47.5) v2(25.91,47.5) v2(25.91,47.5) v2(25.91,47.5) v2(25.91,47.5) v2(25.91,46.99) v2(25.91,46.99) v2(25.91,46.99) v2(25.91,46.99) v2(25.91,46.48) v2(25.91,46.48) v2(25.91,46.48) v2(25.91,46.48) v2(25.91,46.48) v2(25.91,46.48) v2(25.91,46.48) v2(25.91,46.48) v2(25.91,45.97) v2(25.91,45.97) v2(25.91,45.97) v2(25.91,45.97) v2(25.91,45.97) v2(25.91,45.97) v2(25.91,45.97) v2(25.91,45.97) v2(25.91,45.97) v2(25.91,45.97) v2(25.91,45.97) v2(25.91,45.97) v2(25.91,45.47) v2(25.91,45.47) v2(25.91,45.47) v2(25.91,45.47) v2(25.91,44.96) v2(25.91,44.96) v2(25.91,44.96) v2(25.91,44.96) v2(25.91,44.96) v2(25.91,44.96) v2(25.91,44.96) v2(25.91,44.96) v2(25.91,44.45) v2(25.91,44.45) v2(25.91,44.45) v2(25.91,44.45) v2(25.91,43.94) v2(25.91,43.94) v2(25.91,43.94) v2(25.91,43.94) v2(25.91,43.94) v2(25.91,43.94) v2(25.91,43.94) v2(25.91,43.94) v2(25.91,43.43) v2(25.91,43.43) v2(25.91,43.43) v2(25.91,43.43) v2(26.42,48.51) v2(26.42,48.51) v2(26.42,48.51) v2(26.42,48.51) v2(26.42,48.51) v2(26.42,48.51) v2(26.42,48.51) v2(26.42,48.51) v2(26.42,48.01) v2(26.42,48.01) v2(26.42,48.01) v2(26.42,48.01) v2(26.42,47.5) v2(26.42,47.5) v2(26.42,47.5) v2(26.42,47.5) v2(26.42,47.5) v2(26.42,47.5) v2(26.42,47.5) v2(26.42,47.5) v2(26.42,46.99) v2(26.42,46.99) v2(26.42,46.99) v2(26.42,46.99) v2(26.42,46.48) v2(26.42,46.48) v2(26.42,46.48) v2(26.42,46.48) v2(26.42,46.48) v2(26.42,46.48) v2(26.42,46.48) v2(26.42,46.48) v2(26.42,45.97) v2(26.42,45.97) v2(26.42,45.97) v2(26.42,45.97) v2(26.42,45.97) v2(26.42,45.97) v2(26.42,45.97) v2(26.42,45.97) v2(26.42,45.97) v2(26.42,45.97) v2(26.42,45.97) v2(26.42,45.97) v2(26.42,45.47) v2(26.42,45.47) v2(26.42,45.47) v2(26.42,45.47) v2(26.42,44.96) v2(26.42,44.96) v2(26.42,44.96) v2(26.42,44.96) v2(26.42,44.96) v2(26.42,44.96) v2(26.42,44.96) v2(26.42,44.96) v2(26.42,44.45) v2(26.42,44.45) v2(26.42,44.45) v2(26.42,44.45) v2(26.42,43.94) v2(26.42,43.94) v2(26.42,43.94) v2(26.42,43.94) v2(26.42,43.94) v2(26.42,43.94) v2(26.42,43.94) v2(26.42,43.94) v2(26.42,43.43) v2(26.42,43.43) v2(26.42,43.43) v2(26.42,43.43) v2(26.92,48.51) v2(26.92,48.51) v2(26.92,48.51) v2(26.92,48.51) v2(26.92,48.51) v2(26.92,48.51) v2(26.92,48.51) v2(26.92,48.51) v2(26.92,48.01) v2(26.92,48.01) v2(26.92,48.01) v2(26.92,48.01) v2(26.92,47.5) v2(26.92,47.5) v2(26.92,47.5) v2(26.92,47.5) v2(26.92,47.5) v2(26.92,47.5) v2(26.92,47.5) v2(26.92,47.5) v2(26.92,46.99) v2(26.92,46.99) v2(26.92,46.99) v2(26.92,46.99) v2(26.92,46.48) v2(26.92,46.48) v2(26.92,46.48) v2(26.92,46.48) v2(26.92,46.48) v2(26.92,46.48) v2(26.92,46.48) v2(26.92,46.48) v2(26.92,45.97) v2(26.92,45.97) v2(26.92,45.97) v2(26.92,45.97) v2(26.92,45.97) v2(26.92,45.97) v2(26.92,45.97) v2(26.92,45.97) v2(26.92,45.97) v2(26.92,45.97) v2(26.92,45.97) v2(26.92,45.97) v2(26.92,45.47) v2(26.92,45.47) v2(26.92,45.47) v2(26.92,45.47) v2(26.92,44.96) v2(26.92,44.96) v2(26.92,44.96) v2(26.92,44.96) v2(26.92,44.96) v2(26.92,44.96) v2(26.92,44.96) v2(26.92,44.96) v2(26.92,44.45) v2(26.92,44.45) v2(26.92,44.45) v2(26.92,44.45) v2(26.92,43.94) v2(26.92,43.94) v2(26.92,43.94) v2(26.92,43.94) v2(26.92,43.94) v2(26.92,43.94) v2(26.92,43.94) v2(26.92,43.94) v2(26.92,43.43) v2(26.92,43.43) v2(26.92,43.43) v2(26.92,43.43) v2(28.7,12.95) v2(28.7,12.95) v2(28.7,12.95) v2(28.7,12.95) v2(28.7,12.95) v2(28.7,12.95) v2(28.7,12.95) v2(28.7,12.95) v2(28.7,12.45) v2(28.7,12.45) v2(28.7,12.45) v2(28.7,12.45) v2(28.7,11.94) v2(28.7,11.94) v2(28.7,11.94) v2(28.7,11.94) v2(28.7,11.94) v2(28.7,11.94) v2(28.7,11.94) v2(28.7,11.94) v2(28.7,11.43) v2(28.7,11.43) v2(28.7,11.43) v2(28.7,11.43) v2(28.7,10.92) v2(28.7,10.92) v2(28.7,10.92) v2(28.7,10.92) v2(28.7,10.92) v2(28.7,10.92) v2(28.7,10.92) v2(28.7,10.92) v2(28.7,10.41) v2(28.7,10.41) v2(28.7,10.41) v2(28.7,10.41) v2(28.7,10.41) v2(28.7,10.41) v2(28.7,10.41) v2(28.7,10.41) v2(28.7,10.41) v2(28.7,10.41) v2(28.7,10.41) v2(28.7,10.41) v2(28.7,9.91) v2(28.7,9.91) v2(28.7,9.91) v2(28.7,9.91) v2(28.7,9.4) v2(28.7,9.4) v2(28.7,9.4) v2(28.7,9.4) v2(28.7,9.4) v2(28.7,9.4) v2(28.7,9.4) v2(28.7,9.4) v2(28.7,8.89) v2(28.7,8.89) v2(28.7,8.89) v2(28.7,8.89) v2(28.7,8.38) v2(28.7,8.38) v2(28.7,8.38) v2(28.7,8.38) v2(28.7,8.38) v2(28.7,8.38) v2(28.7,8.38) v2(28.7,8.38) v2(28.7,7.87) v2(28.7,7.87) v2(28.7,7.87) v2(28.7,7.87) v2(29.21,12.95) v2(29.21,12.95) v2(29.21,12.95) v2(29.21,12.95) v2(29.21,12.95) v2(29.21,12.95) v2(29.21,12.95) v2(29.21,12.95) v2(29.21,12.45) v2(29.21,12.45) v2(29.21,12.45) v2(29.21,12.45) v2(29.21,11.94) v2(29.21,11.94) v2(29.21,11.94) v2(29.21,11.94) v2(29.21,11.94) v2(29.21,11.94) v2(29.21,11.94) v2(29.21,11.94) v2(29.21,11.43) v2(29.21,11.43) v2(29.21,11.43) v2(29.21,11.43) v2(29.21,10.92) v2(29.21,10.92) v2(29.21,10.92) v2(29.21,10.92) v2(29.21,10.92) v2(29.21,10.92) v2(29.21,10.92) v2(29.21,10.92) v2(29.21,10.41) v2(29.21,10.41) v2(29.21,10.41) v2(29.21,10.41) v2(29.21,10.41) v2(29.21,10.41) v2(29.21,10.41) v2(29.21,10.41) v2(29.21,10.41) v2(29.21,10.41) v2(29.21,10.41) v2(29.21,10.41) v2(29.21,9.91) v2(29.21,9.91) v2(29.21,9.91) v2(29.21,9.91) v2(29.21,9.4) v2(29.21,9.4) v2(29.21,9.4) v2(29.21,9.4) v2(29.21,9.4) v2(29.21,9.4) v2(29.21,9.4) v2(29.21,9.4) v2(29.21,8.89) v2(29.21,8.89) v2(29.21,8.89) v2(29.21,8.89) v2(29.21,8.38) v2(29.21,8.38) v2(29.21,8.38) v2(29.21,8.38) v2(29.21,8.38) v2(29.21,8.38) v2(29.21,8.38) v2(29.21,8.38) v2(29.21,7.87) v2(29.21,7.87) v2(29.21,7.87) v2(29.21,7.87) v2(29.72,12.95) v2(29.72,12.95) v2(29.72,12.95) v2(29.72,12.95) v2(29.72,12.95) v2(29.72,12.95) v2(29.72,12.95) v2(29.72,12.95) v2(29.72,12.45) v2(29.72,12.45) v2(29.72,12.45) v2(29.72,12.45) v2(29.72,11.94) v2(29.72,11.94) v2(29.72,11.94) v2(29.72,11.94) v2(29.72,11.94) v2(29.72,11.94) v2(29.72,11.94) v2(29.72,11.94) v2(29.72,11.43) v2(29.72,11.43) v2(29.72,11.43) v2(29.72,11.43) v2(29.72,10.92) v2(29.72,10.92) v2(29.72,10.92) v2(29.72,10.92) v2(29.72,10.92) v2(29.72,10.92) v2(29.72,10.92) v2(29.72,10.92) v2(29.72,10.41) v2(29.72,10.41) v2(29.72,10.41) v2(29.72,10.41) v2(29.72,10.41) v2(29.72,10.41) v2(29.72,10.41) v2(29.72,10.41) v2(29.72,10.41) v2(29.72,10.41) v2(29.72,10.41) v2(29.72,10.41) v2(29.72,9.91) v2(29.72,9.91) v2(29.72,9.91) v2(29.72,9.91) v2(29.72,9.4) v2(29.72,9.4) v2(29.72,9.4) v2(29.72,9.4) v2(29.72,9.4) v2(29.72,9.4) v2(29.72,9.4) v2(29.72,9.4) v2(29.72,8.89) v2(29.72,8.89) v2(29.72,8.89) v2(29.72,8.89) v2(29.72,8.38) v2(29.72,8.38) v2(29.72,8.38) v2(29.72,8.38) v2(29.72,8.38) v2(29.72,8.38) v2(29.72,8.38) v2(29.72,8.38) v2(29.72,7.87) v2(29.72,7.87) v2(29.72,7.87) v2(29.72,7.87) v2(30.23,12.95) v2(30.23,12.95) v2(30.23,12.95) v2(30.23,12.95) v2(30.23,12.95) v2(30.23,12.95) v2(30.23,12.95) v2(30.23,12.95) v2(30.23,12.45) v2(30.23,12.45) v2(30.23,12.45) v2(30.23,12.45) v2(30.23,11.94) v2(30.23,11.94) v2(30.23,11.94) v2(30.23,11.94) v2(30.23,11.94) v2(30.23,11.94) v2(30.23,11.94) v2(30.23,11.94) v2(30.23,11.43) v2(30.23,11.43) v2(30.23,11.43) v2(30.23,11.43) v2(30.23,10.92) v2(30.23,10.92) v2(30.23,10.92) v2(30.23,10.92) v2(30.23,10.92) v2(30.23,10.92) v2(30.23,10.92) v2(30.23,10.92) v2(30.23,10.41) v2(30.23,10.41) v2(30.23,10.41) v2(30.23,10.41) v2(30.23,10.41) v2(30.23,10.41) v2(30.23,10.41) v2(30.23,10.41) v2(30.23,10.41) v2(30.23,10.41) v2(30.23,10.41) v2(30.23,10.41) v2(30.23,9.91) v2(30.23,9.91) v2(30.23,9.91) v2(30.23,9.91) v2(30.23,9.4) v2(30.23,9.4) v2(30.23,9.4) v2(30.23,9.4) v2(30.23,9.4) v2(30.23,9.4) v2(30.23,9.4) v2(30.23,9.4) v2(30.23,8.89) v2(30.23,8.89) v2(30.23,8.89) v2(30.23,8.89) v2(30.23,8.38) v2(30.23,8.38) v2(30.23,8.38) v2(30.23,8.38) v2(30.23,8.38) v2(30.23,8.38) v2(30.23,8.38) v2(30.23,8.38) v2(30.23,7.87) v2(30.23,7.87) v2(30.23,7.87) v2(30.23,7.87) v2(30.73,12.95) v2(30.73,12.95) v2(30.73,12.95) v2(30.73,12.95) v2(30.73,12.95) v2(30.73,12.95) v2(30.73,12.95) v2(30.73,12.95) v2(30.73,12.45) v2(30.73,12.45) v2(30.73,12.45) v2(30.73,12.45) v2(30.73,11.94) v2(30.73,11.94) v2(30.73,11.94) v2(30.73,11.94) v2(30.73,11.94) v2(30.73,11.94) v2(30.73,11.94) v2(30.73,11.94) v2(30.73,11.43) v2(30.73,11.43) v2(30.73,11.43) v2(30.73,11.43) v2(30.73,10.92) v2(30.73,10.92) v2(30.73,10.92) v2(30.73,10.92) v2(30.73,10.92) v2(30.73,10.92) v2(30.73,10.92) v2(30.73,10.92) v2(30.73,10.41) v2(30.73,10.41) v2(30.73,10.41) v2(30.73,10.41) v2(30.73,10.41) v2(30.73,10.41) v2(30.73,10.41) v2(30.73,10.41) v2(30.73,10.41) v2(30.73,10.41) v2(30.73,10.41) v2(30.73,10.41) v2(30.73,9.91) v2(30.73,9.91) v2(30.73,9.91) v2(30.73,9.91) v2(30.73,9.4) v2(30.73,9.4) v2(30.73,9.4) v2(30.73,9.4) v2(30.73,9.4) v2(30.73,9.4) v2(30.73,9.4) v2(30.73,9.4) v2(30.73,8.89) v2(30.73,8.89) v2(30.73,8.89) v2(30.73,8.89) v2(30.73,8.38) v2(30.73,8.38) v2(30.73,8.38) v2(30.73,8.38) v2(30.73,8.38) v2(30.73,8.38) v2(30.73,8.38) v2(30.73,8.38) v2(30.73,7.87) v2(30.73,7.87) v2(30.73,7.87) v2(30.73,7.87)
G1: length 16.3
  TOP w0.508: Q1.4 40.8,38.45 G1.1
  TOP w0.635: C5.1 39.54,37.43 v1(39.37,37.59) 39.39,37.61 Q1.4 ; R6.1 v1(30.99,31.37)
  LAYER_3 w0.635: v1(30.99,31.37) 33.78,31.37 39.37,36.96 v1(39.37,37.59)
G2: length 19.4
  TOP w0.381: C6.1 39.66,20.15
  TOP w0.508: G2.1 41.06,21.94 Q2.4
  TOP w0.635: R8.1 30.31,27.6 v1(30.35,27.56) ; Q2.4 39.37,21.92 v1(39.37,21.03) 39.37,20.45 39.66,20.15
  LAYER_3 w0.635: v1(30.35,27.56) 30.35,23.37 32.72,21.01 39.34,21.01 v1(39.37,21.03)
UNNAMED_2_ADLTC7067_I79_FLTN: length 20.6
  TOP w0.381: TP11.1 6.22,31.62 19.77,31.62 R2.2 21.35,30.04 U1.3
UNNAMED_2_ADLTC7067_I79_G1: length 1.9
  TOP w0.381: U1.11 27.52,30.69 27.58,30.76 27.6,30.76 28.21,31.37 R6.2
UNNAMED_2_ADLTC7067_I79_G1IN: length 24.9
  TOP w0.381: TP1.1 9.52,45.09 22.79,31.82 U1.1
UNNAMED_2_ADLTC7067_I79_G1VCC: length 2.3
  TOP w0.381: U1.12 27.06,31.34 R7.2
UNNAMED_2_ADLTC7067_I79_G2: length 1.8
  TOP w0.381: R8.2 28.19,28.74 U1.8
UNNAMED_2_ADLTC7067_I79_G2IN: length 21.5
  TOP w0.381: TP2.1 10.67,36.83 14.1,33.4 19.43,33.4 21.21,31.62 21.32,31.62 22.19,30.76 22.47,30.76 22.53,30.69 U1.2
UNNAMED_2_ADLTC7067_I79_G2VCC: length 1.7
  TOP w0.381: R5.1 22.49,26.57 22.49,27.82 22.76,28.09 U1.6
UNNAMED_2_CAP_I57_N1: length 12.1
  TOP w1.27: C13.P 72.9,41.91 TP7.1
UNNAMED_2_CAP_I59_N1: length 12
  TOP w1.27: C14.P 73.15,27.94 TP8.1
UNNAMED_2_DIOSCHOTTKY_I25_N: length 8.5
  TOP w0.381: C4.1 31.37,29.84 31.75,30.23 31.75,32 30.86,32.89 R7.1 30.35,32.93 30.35,34.04 29.46,34.92 D6.C

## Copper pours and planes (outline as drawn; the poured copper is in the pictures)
GND_SIGNAL on TOP: 1.27,62.23 93.98,62.23 93.98,1.27 28.07,1.27 28.07,6.86 27.43,6.86 27.43,1.27 1.27,1.27 ; 7 cut-outs
GND_SIGNAL on BOTTOM: 1.27,62.23 1.27,1.27 93.98,1.27 93.98,62.23 ; 3 cut-outs
GND_SIGNAL on LAYER_2: 1.27,62.23 93.98,62.23 93.98,1.27 1.27,1.27
GND_SIGNAL on LAYER_3: 1.4,1.27 1.4,62.23 93.98,62.23 93.98,1.27 ; 5 cut-outs
VCC on TOP: 20.07,27.81 20.07,25.91 19.56,25.4 19.05,25.4 19.05,24.26 12.95,18.16 1.27,18.16 1.27,9.14 10.67,9.14 21.59,20.07 21.59,27.69 21.34,27.94 20.19,27.94
VIN_OPT on TOP: 18.29,62.23 18.29,40.64 30.35,40.64 30.35,47.62 42.42,47.62 42.42,62.23
VIN_OPT on TOP: 26.67,25.53 26.67,23.24 23.5,23.24 23.5,6.99 31.88,6.99 31.88,25.53
VIN_OPT on BOTTOM: 34.95,58.93 33.91,57.99 33.91,54.86 30.48,51.44 23.24,51.44 22.48,50.67 22.48,43.18 25.02,40.64 29.97,40.64 32.38,38.23 32.38,19.3 27.05,13.97 27.05,7.37 27.94,6.48 35.81,6.48 36.7,7.37 36.7,49.15 40.39,52.83 40.39,57.66 39.12,58.93
Q1_D on TOP: 30.86,47.24 30.86,39.62 42.16,39.62 42.16,47.24
Q2_D on TOP: 32.26,29.84 32.26,23.11 42.16,23.11 42.16,29.84
UNNAMED_2_CAP_I57_N1 on TOP: 42.8,49.53 42.8,37.47 75.06,37.47 75.06,49.53
UNNAMED_2_CAP_I59_N1 on TOP: 42.8,20.95 43.31,20.45 50.16,20.45 51.82,22.1 73.91,22.1 74.55,22.73 74.55,28.19 73.15,29.59 42.8,29.59
UNNAMED_2_DIOSCHOTTKY_I13_N on TOP: 23.37,27.05 23.37,25.91 22.61,25.15 22.1,25.15 22.1,23.62 26.29,23.62 26.29,27.05

Small or netless copper shapes (teardrops, artwork), in the pictures only: 8 on TOP

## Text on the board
BOTTOM: 08-072118 REV B
TOP: 08-072118 REV B
Ref Des/Silkscreen Top: VOUT1 | VOUT2 | FAULT | SGND | G2IN | G1IN | VCC | VIN_OPT | PGND | 150V DUAL HIGH-SIDE MOSFET GATE DRIVER | EVAL-LTC7067-AZ
PAGE_OUTLINE: DATE: 2-1-2023 | B | ECR-112470 | 1-17-2023 | X
User.15: 0.0035" | INNER LAYER   (LAYER 2) | INNER LAYER   (LAYER 3) | PER IPC-4552 LATEST REVISION | ENIG (Electroless Nickel/Immersion Gold)
User.17: L2 | 08-      -08
User.18: L3 | 08-      -09
User.23: POWER | GATE | MONITOR | Ivcc | VCC | VOLTMETER | SUPPLY | INPUT | FAULT FLAG | MONITOR GATE | VOLTAGE | A | V | - | +
User.24: INPUT | PWM | POWER | MONITOR | Ivcc | VCC | SUPPLY | FAULT FLAG | MONITOR GATE | OSCILLOSCOPE | OUTPUTS | A | V | - | +
User.45: FIGURE | SIZE | 10.0 | 12.0 | 45.0 | 100.0 | 187.0 | PLATED | NON-PLATED | FINISHED HOLES IN MILS | ALL UNITS ARE IN MILS | QTY | 1469 | 8 | 2 | 11 | 4 | TOLERANCE/NOTES
